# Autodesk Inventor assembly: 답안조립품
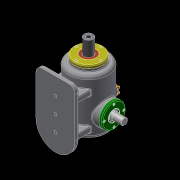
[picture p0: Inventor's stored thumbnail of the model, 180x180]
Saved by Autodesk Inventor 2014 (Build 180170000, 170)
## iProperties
Created: 2018-04
Part Number: 답안조립품
Document SubType Name: Assembly
Designer: 703
Author: 703
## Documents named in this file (17)
- C:\Users\user\Desktop\380407V1022\답안조립품.iam
- C:\Users\user\Desktop\380407V1022\베어링 6205.ipt
- 베어링 6205.ipt
- C:\Users\user\Desktop\380407V1022\본체.ipt
- C:\Users\user\Desktop\380407V1022\볼트 M4.ipt
- 볼트 M4.ipt
- C:\Users\user\Desktop\380407V1022\부시.ipt
- C:\Users\user\Desktop\380407V1022\상부 캡.ipt
- C:\Users\user\Desktop\380407V1022\슬라이드 커버.ipt
- C:\Users\user\Desktop\380407V1022\슬라이드.ipt
- C:\Users\user\Desktop\380407V1022\오일실.ipt
- 오일실.ipt
- C:\Users\user\Desktop\380407V1022\축 커버-1.ipt
- C:\Users\user\Desktop\380407V1022\축 커버-2.ipt
- C:\Users\user\Desktop\380407V1022\편심축.ipt
- C:\Users\user\Desktop\380407V1022\플레이트.ipt
- C:\Users\user\Desktop\380407V1022\가변스프링.ipt
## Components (2 placed, 2 different names)
1. 플레이트:1
2. 가변스프링:1
